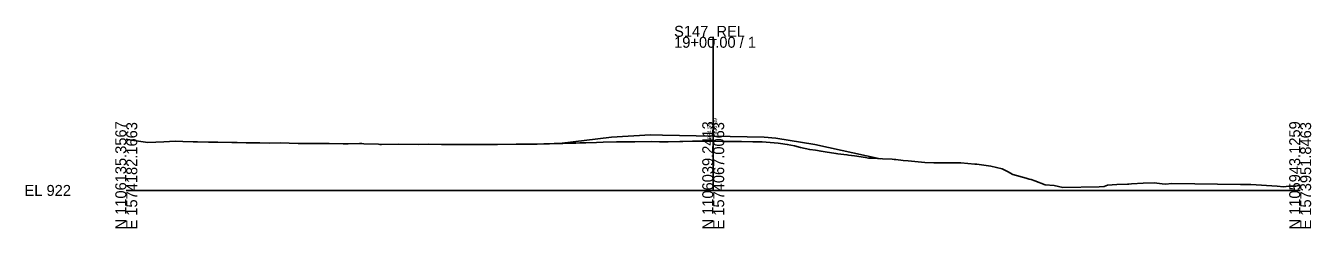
# Model space of a CAD drawing. Extents: x 1557985 to 1558314, y 1113650 to 1118205.
# Drawn here: x 1557985.4 to 1558314, y 1116150.1 to 1116202 of the extents above; entities that cross this region are included whole.
import ezdxf

# ---------------------------------------------------------------- set-up
doc = ezdxf.new("R2010")
doc.units = 0
for name, color, linetype in [('RD_GPK_XS_Cell', 7, 'Continuous'), ('RD_XS_EarthShd', 7, 'Continuous'), ('RD_XS_ExGround', 7, 'Continuous'), ('RD_XS_Pave', 7, 'Continuous'), ('RD_XS_TieSlope', 7, 'Continuous'), ('RD_XS_TX_Elev_EX', 7, 'Continuous'), ('RD_XS_TX_Elev_PR', 7, 'Continuous')]:
    doc.layers.add(name, color=color, linetype=linetype)

msp = doc.modelspace()

# ---------------------------------------------------------------- linework, layer by layer
at = {"layer": 'RD_GPK_XS_Cell'}
for p, q in [((1558161.13, 1116159.8), (1558161.13, 1116199.11)), ((1558011.13, 1116159.8), (1558161.13, 1116159.8)), ((1558161.13, 1116159.8), (1558311.13, 1116159.8))]:
    msp.add_line(p, q, dxfattribs=at)
at = {"layer": 'RD_XS_EarthShd'}
for p, q in [((1558135.13, 1116173.41), (1558121.87, 1116171.81)), ((1558145.13, 1116174.01), (1558135.13, 1116173.41)), ((1558148.13, 1116173.95), (1558145.13, 1116174.01)), ((1558174.13, 1116173.43), (1558177.13, 1116173.19))]:
    msp.add_line(p, q, dxfattribs=at)
at = {"layer": 'RD_XS_ExGround'}
msp.add_lwpolyline([(1558011.13, 1116172.9), (1558012.45, 1116172.64), (1558016.6, 1116172.06), (1558020.7, 1116172.25), (1558023.66, 1116172.38), (1558025.58, 1116172.3), (1558028.27, 1116172.24), (1558029.3, 1116172.24), (1558032.13, 1116172.17), (1558034.19, 1116172.12), (1558034.51, 1116172.12), (1558038.15, 1116172.09), (1558038.74, 1116172.07), (1558039.46, 1116172.07), (1558041.77, 1116171.98), (1558043.58, 1116171.96), (1558044.41, 1116171.95), (1558045.24, 1116171.96), (1558047.81, 1116171.93), (1558050.46, 1116171.96), (1558052.72, 1116171.92), (1558055.03, 1116171.84), (1558058.89, 1116171.84), (1558059.62, 1116171.83), (1558061.71, 1116171.82), (1558062.96, 1116171.82), (1558066.57, 1116171.76), (1558067.88, 1116171.75), (1558070.71, 1116171.77), (1558071.33, 1116171.77), (1558071.87, 1116171.76), (1558075.55, 1116171.6), (1558075.9, 1116171.59), (1558076.33, 1116171.58), (1558080.73, 1116171.65), (1558085.78, 1116171.59), (1558088.28, 1116171.61), (1558091.73, 1116171.54), (1558092.79, 1116171.53), (1558093.65, 1116171.56), (1558098.48, 1116171.57), (1558100.31, 1116171.56), (1558101.6, 1116171.55), (1558101.99, 1116171.55), (1558106.01, 1116171.58), (1558110.73, 1116171.62), (1558111.63, 1116171.63), (1558115.09, 1116171.66), (1558116.14, 1116171.67), (1558117.85, 1116171.72), (1558119.33, 1116171.75), (1558120.46, 1116171.82), (1558122.69, 1116171.84), (1558124.35, 1116171.87), (1558126.06, 1116171.92), (1558127.07, 1116171.94), (1558128.3, 1116171.97), (1558128.6, 1116171.98), (1558131.29, 1116172.06), (1558132.99, 1116172.12), (1558136.43, 1116172.2), (1558137.6, 1116172.24), (1558138.1, 1116172.25), (1558138.68, 1116172.25), (1558139.53, 1116172.25), (1558141.06, 1116172.26), (1558145.48, 1116172.31), (1558147.4, 1116172.24), (1558148.66, 1116172.22), (1558149.58, 1116172.25), (1558152.58, 1116172.34), (1558153.35, 1116172.35), (1558155.84, 1116172.37), (1558156.54, 1116172.38), (1558156.87, 1116172.38), (1558158.8, 1116172.4), (1558160.08, 1116172.4), (1558161.13, 1116172.38), (1558163.41, 1116172.35), (1558165.04, 1116172.35), (1558165.49, 1116172.35), (1558167.85, 1116172.31), (1558168.37, 1116172.3), (1558171.23, 1116172.22), (1558171.93, 1116172.24), (1558173.61, 1116172.26), (1558177.73, 1116171.85), (1558178.3, 1116171.8), (1558180.05, 1116171.57), (1558181.87, 1116171.21), (1558183.47, 1116170.81), (1558185.79, 1116170.24), (1558187.25, 1116170.07), (1558188.7, 1116169.82), (1558189.75, 1116169.66), (1558192.49, 1116169.28), (1558192.95, 1116169.2), (1558195.3, 1116168.91), (1558195.69, 1116168.84), (1558197.24, 1116168.62), (1558200.02, 1116168.19), (1558200.85, 1116168.09), (1558201.84, 1116168.02), (1558204.37, 1116167.9), (1558206.87, 1116167.79), (1558207.38, 1116167.75), (1558207.8, 1116167.72), (1558209.67, 1116167.48), (1558210.96, 1116167.35), (1558215.18, 1116166.91), (1558217.51, 1116166.87), (1558218.71, 1116166.83), (1558219.54, 1116166.82), (1558221.39, 1116166.84), (1558224.39, 1116166.9), (1558228, 1116166.54), (1558228.48, 1116166.5), (1558232.06, 1116166.03), (1558234.98, 1116165.36), (1558236.29, 1116164.63), (1558237.67, 1116163.87), (1558241.09, 1116162.9), (1558241.86, 1116162.68), (1558242.42, 1116162.56), (1558243.29, 1116162.26), (1558245.94, 1116161.19), (1558248.24, 1116161.05), (1558250.5, 1116160.51), (1558259.74, 1116160.74), (1558261, 1116160.78), (1558261.89, 1116161.14), (1558264.29, 1116161.32), (1558267, 1116161.41), (1558267.35, 1116161.38), (1558268.06, 1116161.47), (1558271, 1116161.68), (1558273.78, 1116161.72), (1558275.87, 1116161.51), (1558276.73, 1116161.38), (1558278.32, 1116161.54), (1558295.88, 1116161.34), (1558298.5, 1116161.31), (1558305.24, 1116160.91), (1558306.86, 1116160.69), (1558308.25, 1116160.86), (1558309.04, 1116160.89), (1558309.65, 1116160.87), (1558310.02, 1116160.93), (1558311.13, 1116161.11)], dxfattribs=at)
at = {"layer": 'RD_XS_Pave'}
for p, q in [((1558161.13, 1116173.69), (1558148.13, 1116173.95)), ((1558174.13, 1116173.43), (1558161.13, 1116173.69))]:
    msp.add_line(p, q, dxfattribs=at)
at = {"layer": 'RD_XS_TieSlope'}
for p, q in [((1558177.13, 1116173.19), (1558187.13, 1116171.59)), ((1558187.13, 1116171.59), (1558203.77, 1116167.92))]:
    msp.add_line(p, q, dxfattribs=at)

# ---------------------------------------------------------------- texts
at = {"layer": 'RD_GPK_XS_Cell'}
for s, p in [('S147_REL', (1558151.13, 1116199.11)), ('19+00.00 / 1', (1558151.13, 1116196.31)), ('EL 922', (1557985.13, 1116158.4))]:
    msp.add_text(s, height=2.8, dxfattribs=at).set_placement(p)
for s, p in [('N 1106135.3567', (1558011.13, 1116149.8)), ('E 1574182.1663', (1558013.93, 1116149.8)), ('N 1106039.2413', (1558161.13, 1116149.8)), ('E 1574067.0063', (1558163.93, 1116149.8)), ('N 1105943.1259', (1558311.13, 1116149.8)), ('E 1573951.8463', (1558313.93, 1116149.8))]:
    msp.add_text(s, height=2.8, rotation=90, dxfattribs=at).set_placement(p)
at = {"layer": 'RD_XS_TX_Elev_EX'}
msp.add_text('934.59', height=1, rotation=90, dxfattribs=at).set_placement((1558160.63, 1116172.88))
at = {"layer": 'RD_XS_TX_Elev_PR'}
msp.add_text(' 935.89', height=1, rotation=90, dxfattribs=at).set_placement((1558162.13, 1116173.69))

doc.saveas('drawing.dxf')
